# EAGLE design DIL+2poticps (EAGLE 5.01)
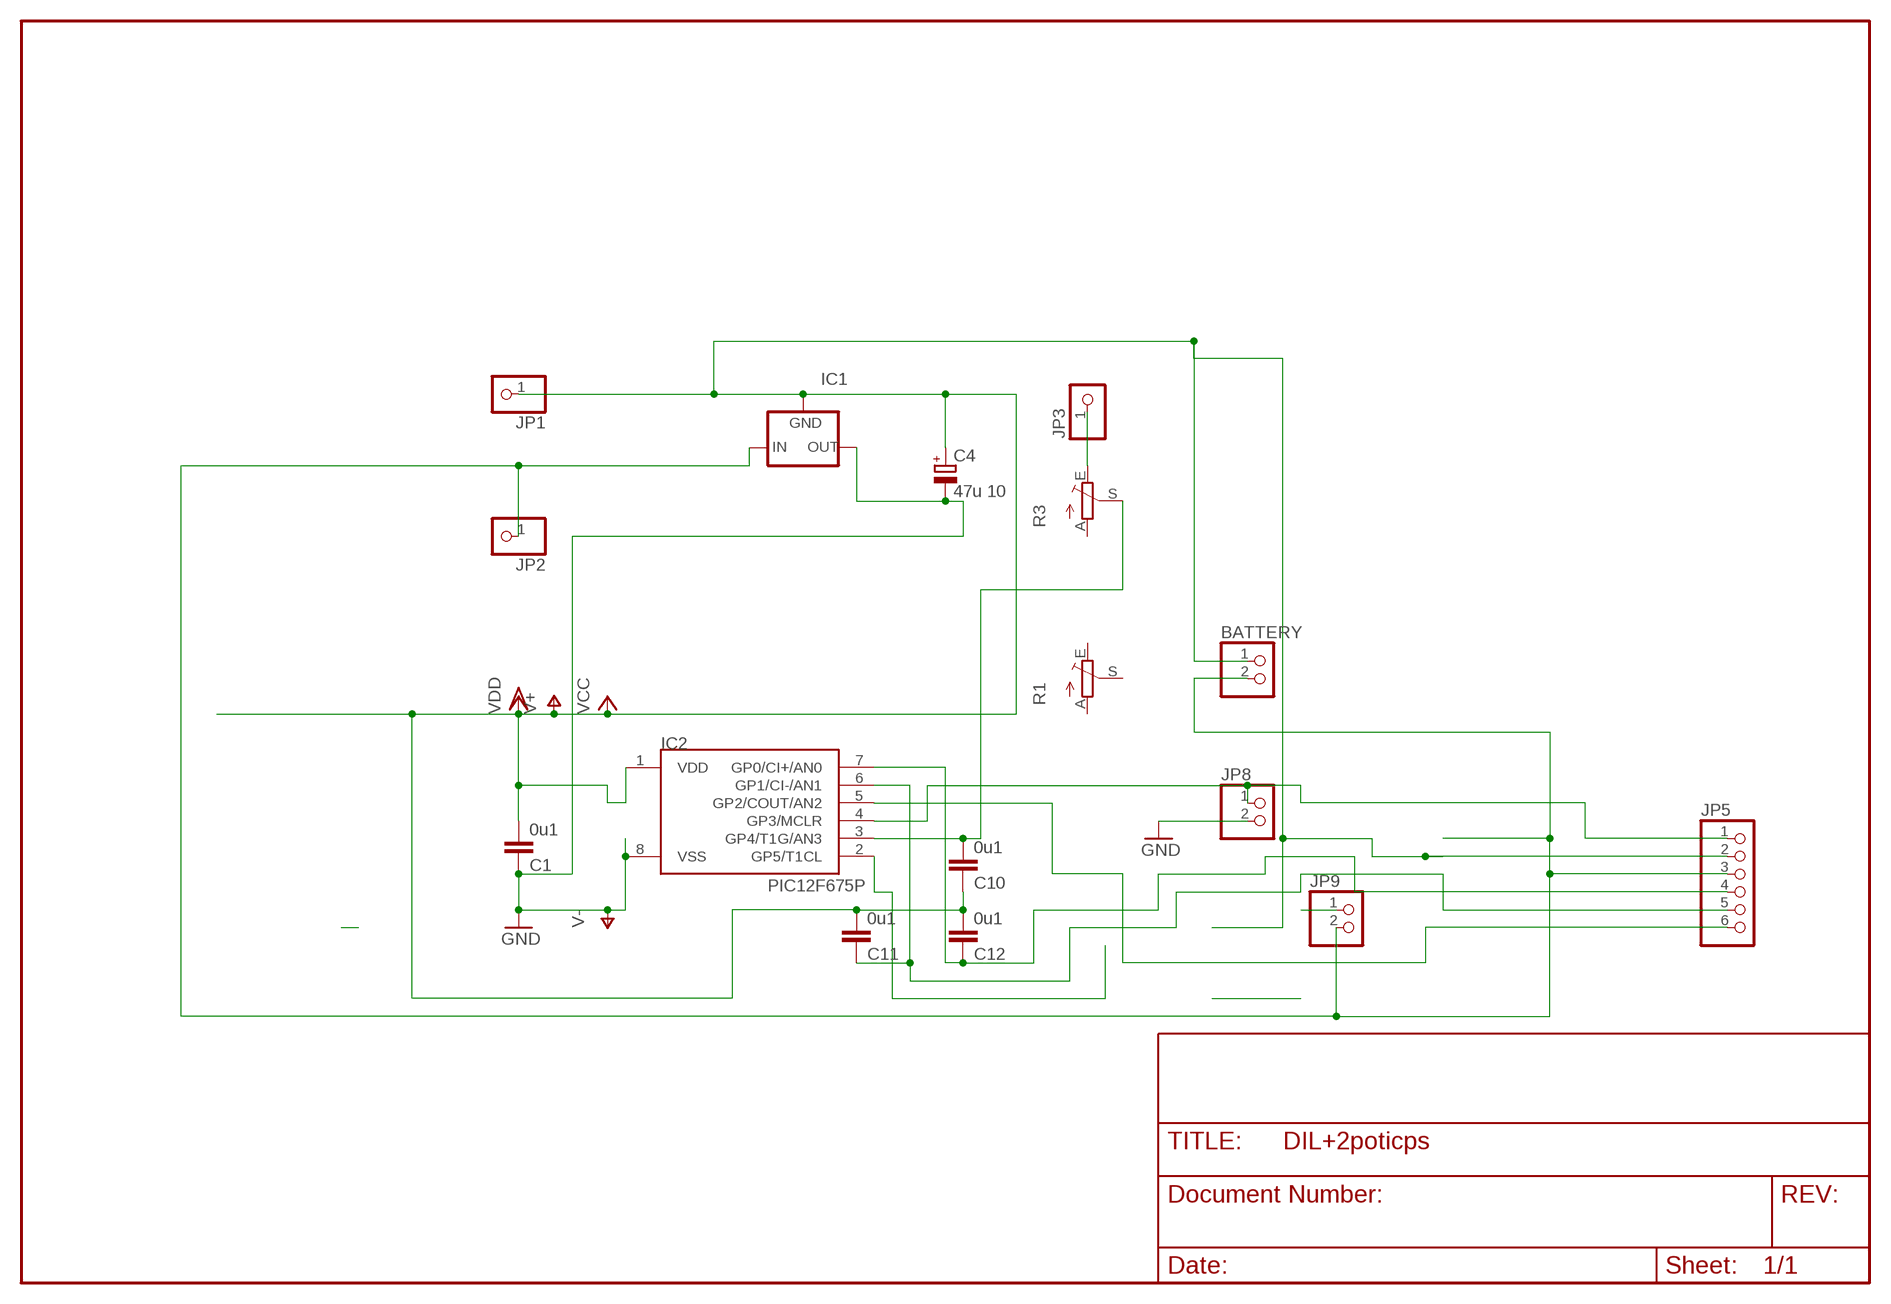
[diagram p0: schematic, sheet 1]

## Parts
BATTERY  PINHD-1X2  [1X02]
C1  0u1  C-EUC1206  [C1206]
C4  47u 10  CPOL-EUE2.5-6  [E2,5-6]
C10  0u1  C-EUC1206  [C1206]
C11  0u1  C-EUC1206  [C1206]
C12  0u1  C-EUC1206  [C1206]
IC1  79LXX  [79LXX]
IC2  PIC12F675P  [DIL8]
JP1  PINHD-1X1  [1X01]
JP2  PINHD-1X1  [1X01]
JP3  PINHD-1X1  [1X01]
JP5  PINHD-1X6  [1X06]
JP8  PINHD-1X2  [1X02]
JP9  PINHD-1X2  [1X02]
R1  TRIM_EU-CA6V  [CA6V]
R3  TRIM_EU-CA6V  [CA6V]

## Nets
GND: C1.1 C4.- IC1.OUT IC2.8(VSS) JP8.2 ; supply symbol labelled V-
N$1: JP3.1 R3.E
N$2: IC2.5(GP2/COUT/AN2) JP5.6
N$3: IC2.4(GP3/MCLR) JP5.1 JP8.1
N$4: JP9.1
N$7: BATTERY.2 IC1.IN JP2.1 JP5.3 JP9.2
N$8: IC2.2(GP5/T1CL)
N$12: C10.2 IC2.3(GP4/T1G/AN3) R3.S
N$13: C12.1 IC2.7(GP0/CI+/AN0) JP5.4
N$15: C11.1 IC2.6(GP1/CI-/AN1) JP5.5
V+: BATTERY.1 C1.2 C4.+ C10.1 C11.2 C12.2 IC1.GND IC2.1(VDD) JP1.1 JP5.2 ; supply symbol labelled VCC, VDD
Unconnected: R1.A R1.E R1.S R3.A

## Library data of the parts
BATTERY JP8 JP9 = pinhead:PINHD-1X2: PIN HEADER
C1 C10-C12 = rcl:C-EU: CAPACITOR, European symbol
C4 = rcl:CPOL-EU: POLARIZED CAPACITOR, European symbol
IC1 = v-reg:79LXX: VOLTAGE REGULATOR
IC2 = microchip-3:PIC12F6*: uPC nW 1k Program Flash memory 2x Timer Comparator 10b A/D converter/ 4xIN
JP1-JP3 = pinhead:PINHD-1X1: PIN HEADER
JP5 = pinhead:PINHD-1X6: PIN HEADER
R1 R3 = pot:TRIM_EU-: POTENTIOMETER

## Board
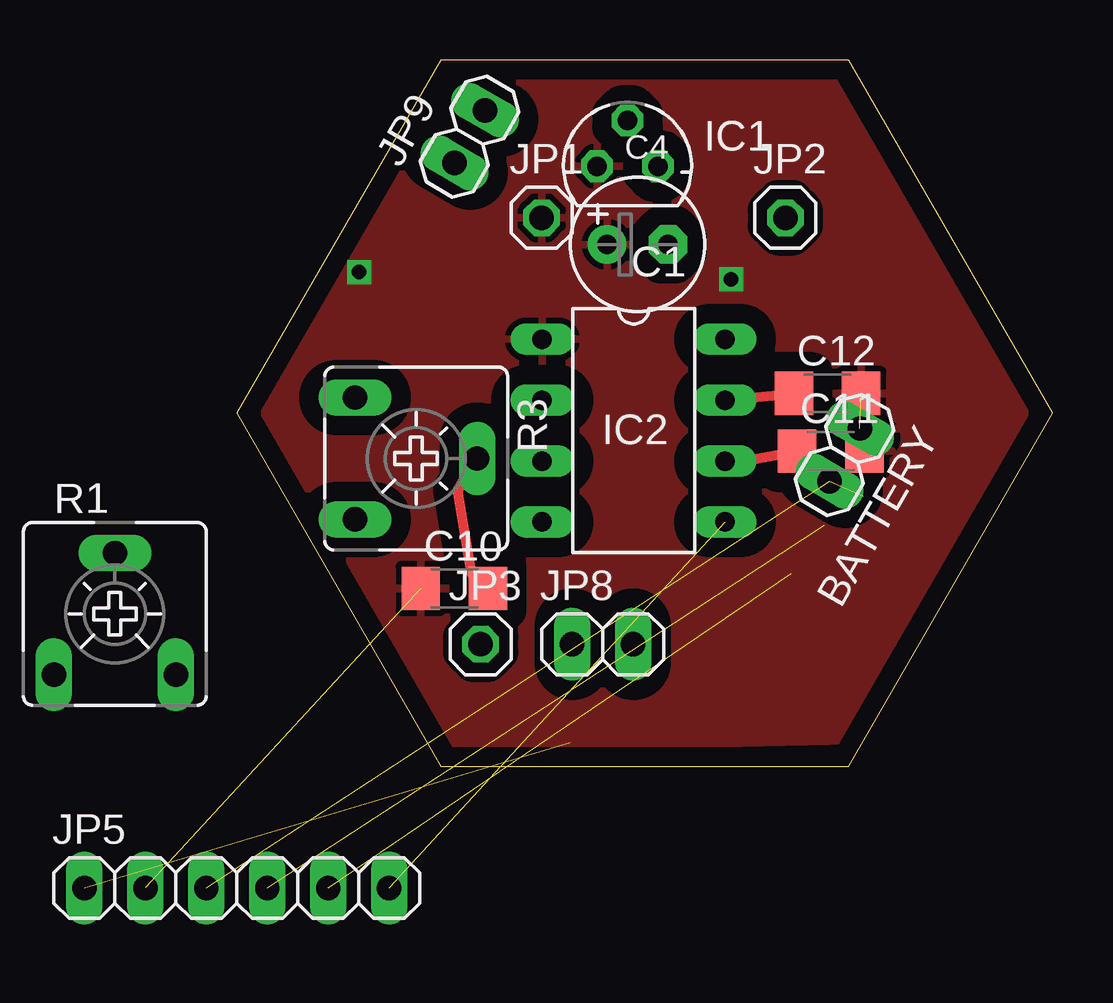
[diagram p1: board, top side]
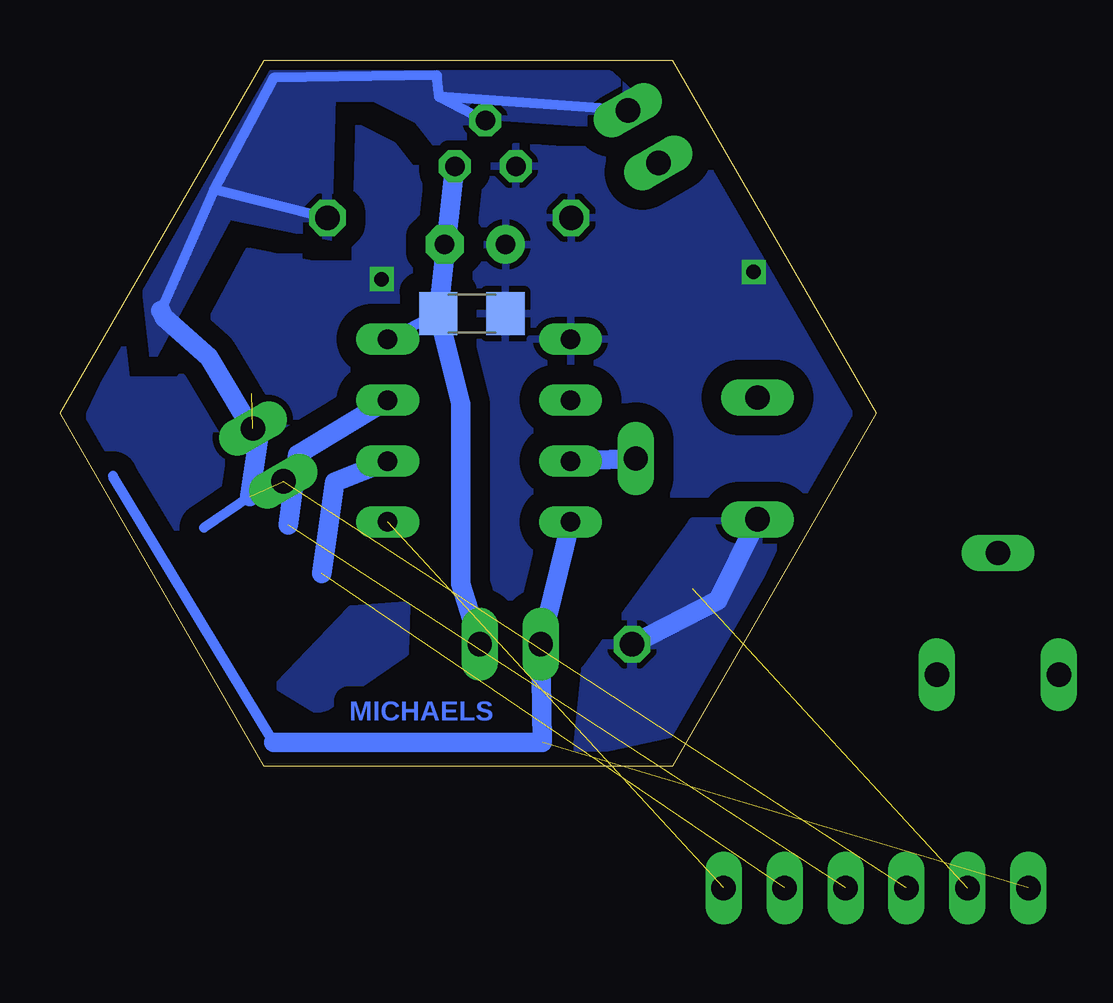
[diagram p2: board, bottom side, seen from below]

Size 34 x 29.44 mm. Coordinates in mm from the lower left corner, seen from the top.
Outline: 8.5,0 25.5,0 34,14.72 25.5,29.44 8.5,29.44 0,14.72 8.5,0
Copper layers (1*16): Top 0.035mm / dielectric 1.5mm / Bottom 0.035mm
Design rules "default *": minimum track width 10mil, minimum drill 24mil, track to track 8mil, track to pad 8mil, pad to pad 8mil, via to via 8mil, smd to smd 8mil, copper to edge 10mil, drill to drill 8mil, minimum pad ring 10mil, minimum via ring 8mil, stop-mask expansion 4mil, vias tented up to drill 0mil, thermal gap 10mil

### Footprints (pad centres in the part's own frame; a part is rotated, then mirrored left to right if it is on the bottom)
1X02 = drill 1.016 long: 1 -1.27,0; 2 1.27,0
C1206 = smd 1.6 x 1.8: 1 -1.4,0; 2 1.4,0
E2,5-6 = drill 0.813 pad 1.6 round: + -1.27,0 | drill 0.813 pad 1.6 octagon: - 1.27,0
79LXX = drill 0.813 octagon: GND -1.27,0; IN 0,1.905; OUT 1.27,0
DIL8 = drill 0.813 long: 1 -3.81,-3.81; 2 -1.27,-3.81; 3 1.27,-3.81; 4 3.81,-3.81; 5 3.81,3.81; 6 1.27,3.81; 7 -1.27,3.81; 8 -3.81,3.81
1X01 = drill 1.016 octagon: 1 0,0
1X06 = drill 1.016 long: 1 -6.35,0; 2 -3.81,0; 3 -1.27,0; 4 1.27,0; 5 3.81,0; 6 6.35,0
CA6V = drill 1.016 long: A -2.54,-2.54; E 2.54,-2.54; S 0,2.54

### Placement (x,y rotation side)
BATTERY  25.33,12.98 240 top
C1  16.84,18.86 0 bottom
C4  16.7,21.75 0 top
C10  9.07,7.41 0 top
C11  24.75,13.14 0 top
C12  24.61,15.54 0 top
IC1  16.28,25.01 0 top
IC2  16.54,13.99 270 top
JP1  12.7,22.86 0 top
JP2  22.86,22.86 0 top
JP3  10.16,5.08 0 top
JP5  not placed on the board
JP8  15.24,5.08 0 top
JP9  9.71,26.24 60 top
R1  -5.08,6.35 0 top
R3  7.47,12.83 270 top

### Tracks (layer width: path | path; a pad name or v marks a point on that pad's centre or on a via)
GND
  Bottom 0.406: C1.1 IC2.8 | 18.07,20.35 C4.-
  Bottom 0.813: JP8.2 17.3,7.6 17.3,15.1 C1.1 18.07,20.35 IC1.OUT
N$1
  Bottom 0.813: JP3.1 6.6,6.9 R3.E
  pour Bottom (isolate 0.61): 5.08,10.16 7.62,10.16 12.1,4 12.45,0.55 7.85,1.55 3.7,10.35
N$2  (1 unrouted)
  pour Bottom (isolate 0.61): 22.86,2.54 19.65,4.75 19.6,6.65 21.85,6.5 24.85,3.35 23.3,2.4
N$3  (1 unrouted)
  Bottom 0.406: 25.1,1 31.8,12.1
  Bottom 0.813: IC2.4 JP8.1 13.9,1 25.1,1
N$7  (2 unrouted)
  Bottom 0.406: 27.58,24.05 29.8,19 | 27.58,24.05 25.1,28.7 18.3,28.8 18.2,27.9 | 18.2,27.9 IC1.IN | JP9.2 18.2,27.9 | 27.58,24.05 JP2.1 | 26.1,11.25 28,9.95
  Bottom 0.813: 29.8,19 29.65,18.7 27.8,17.05 25.75,13.6 26.1,11.25
  pour Bottom (isolate 0.406, rank 2): 10.16,27.94 11.1,28.8 25.2,29 30.45,20.35 30.1,17.2 27,23 22.6,22.1 22.8,24.1 22.7,27.9 20.9,27.9 19.1,27 18.2,25.85 16.9,25.85 17,27.2 11.3,26.8
N$12
  Top 0.406: R3.S 9.2,11.5 9.8,8 C10.2
  Bottom 0.813: R3.S IC2.3
N$13  (1 unrouted)
  Top 0.406: IC2.7 C12.1
  Bottom 0.813: IC2.7 24.1,13 24.5,10.05
N$15  (1 unrouted)
  Top 0.406: C11.1 21.13,12.73 IC2.6
  Bottom 0.813: IC2.6 22.55,11.85 23.1,8.04
V+  (via drill 0.6)  (2 unrouted)
  other vias: 20.6,20.3 5.1,20.6
  pour Bottom (isolate 0.813, rank 4): 25.09,0.65 6.94,0.85 -0.63,14.71 7.94,28.25 23.9,28.98 28.25,24.24 33.14,13.91
  pour Top (isolate 0.813, rank 4): 25.05,28.74 33.52,14.83 25.59,1.05 7.24,0.65 -0.28,14.57 9.11,28.44

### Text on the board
Bottom: MICHAELS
